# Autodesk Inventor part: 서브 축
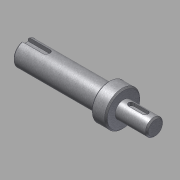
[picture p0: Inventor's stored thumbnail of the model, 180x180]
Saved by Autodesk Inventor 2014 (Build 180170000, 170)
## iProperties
Created: 2014-10
Part Number: 서브 축
Document SubType Name: Modeling
Designer: KYOUNG IL JANG
Density: 1 g/cm^3
Mass: 19.9624 g
Surface Area: 57.7178 cm^2
Volume: 19.9624 cm^3
Material: 강철, 연강
Appearance: 금속-강(스테인리스, 브러시됨)
Author: SeoGD™ [www.esajin.kr]
Revision Number: 1
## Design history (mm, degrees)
sketch "스케치1"
  geometry: L1 (-16.331, 0)-(-108.831, 0); L2 (-16.331, 0)-(-16.331, -6); L3 (-16.331, -6)-(-38.831, -6); L4 (-38.831, -12.5)-(-46.5, -12.5); L5 (-46.5, -8.5)-(-108.831, -8.5); L6 (-108.831, -8.5)-(-108.831, 0); L7 (-46.5, -8.5)-(-46.5, -12.5); L8 (-38.831, -6)-(-38.831, -12.5); L9 (-46.5, 12.249)-(-46.5, -12.249) reference; L10 (-38.831, -17)-(-38.831, 17) reference; 2 further points
  constraints: 17 end point, 4 perpendicular, 2 collinear, 2 parallel, 1 horizontal, 1 midpoint, 1 point on line
  dimensions: "d1" = 12 diameter of L3 L1; "d2" = 25 diameter of L4 L1; "d3" = 17 diameter of L5 L1; "d18" = 22.5 distance of L2.end L3.end; "d20" = 70 distance between parallel lines of L6 L8; "d21" = 7.66872 distance of L4.start L4.end (derived)
revolve "회전1" sketch "스케치1" stored, may be unused: angle "d5" = 90 deg
chamfer "모따기1" distance "d6" = 1; stored, may be unused: second distance "d7" = 2, angle "d8" = 45 deg
node "작업 평면1"
sketch "스케치2"
  geometry: L1 (11.25, 5)-(11.25, -5) reference; L2 (-5.75, -2)-(4.25, -2); L3 (4.25, 2)-(-5.75, 2); A1 r 2 centre (4.25, 0) between (4.25, -2) and (4.25, 2); A2 r 2 centre (-5.75, 0) between (-5.75, 2) and (-5.75, -2); 2 further points
  constraints: 4 end point, 4 point on circle, 4 tangent, 2 centre point, 1 horizontal alignment, 1 midpoint, 1 parallel, 1 perpendicular
  dimensions: "d9" = 4 distance between parallel lines of L2 L3; "d10" = 14 dimension on A1 A2; "d11" = 5 distance edge to line of A1 L1
extrude "돌출1" cut sketch "스케치2" distance "d12" = 2.5; taper "d13" = 0 deg
node "작업 평면2"
sketch "스케치3"
  geometry: L1 (-31.166, -7.5)-(-31.166, 7.5) reference; L2 (-31.166, 2.5)-(-15.666, 2.5); L3 (-15.666, -2.5)-(-31.166, -2.5); A1 r 2.5 centre (-15.666, 0) between (-15.666, -2.5) and (-15.666, 2.5); 2 further points
  constraints: 4 end point, 2 perpendicular, 2 point on circle, 2 point on line, 2 tangent, 1 centre point, 1 horizontal alignment, 1 midpoint
  dimensions: "d14" = 5 distance between parallel lines of L3 L2; "d15" = 18 dimension on A1 L1
extrude "돌출2" cut sketch "스케치3" distance "d16" = 3; taper "d17" = 0 deg
sketch "스케치4"
  geometry: C1 r 12.5 at (0, 0) reference; 1 further point
extrude "돌출3" join sketch "스케치4" distance "d22" = 3; taper "d23" = 0 deg
chamfer "모따기2" distance "d24" = 1; stored, may be unused: second distance "d25" = 2, angle "d26" = 45 deg
node "솔리드1"
node "참조4"
node "참조5"
